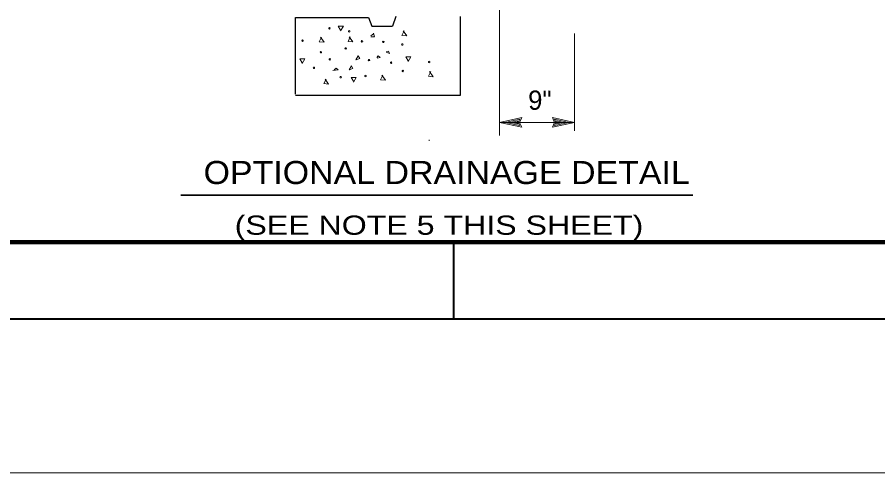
# Model space of a CAD drawing. Extents: x -22.3 to 19.7, y -11.8 to 18.2.
# Drawn here: x -0.15 to 5.45, y -11.84 to -8.88 of the extents above; entities that cross this region are included whole.
import ezdxf
from ezdxf.enums import TextEntityAlignment as Align

# ---------------------------------------------------------------- set-up
doc = ezdxf.new("R2010")
doc.units = 0
doc.header["$LTSCALE"] = 0.05
doc.layers.add('1', color=7, linetype='Continuous', lineweight=13)
doc.layers.add('2', color=7, linetype='Continuous', lineweight=13)

msp = doc.modelspace()

# ---------------------------------------------------------------- linework, layer by layer
at = {"layer": '1'}
for p, q in [((2.99058, -8.52869), (2.99058, -9.64669)), ((3.47858, -8.98169), (3.47858, -9.61469)), ((2.99058, -9.56069), (3.13458, -9.52969)), ((2.99058, -9.56069), (3.47858, -9.56069)), ((2.99058, -9.56069), (3.13458, -9.59169)), ((3.02758, -9.56069), (3.12158, -9.54069)), ((3.02758, -9.56069), (3.12158, -9.58069)), ((3.06358, -9.56069), (3.10858, -9.55069)), ((3.06358, -9.56069), (3.10858, -9.56969)), ((3.10858, -9.55069), (3.10458, -9.56069)), ((3.10458, -9.56069), (3.10858, -9.56969)), ((3.12158, -9.54069), (3.11258, -9.56069)), ((3.11258, -9.56069), (3.12158, -9.58069)), ((3.47858, -9.56069), (3.33458, -9.52969)), ((3.47858, -9.56069), (3.33458, -9.59169)), ((3.44158, -9.56069), (3.34758, -9.54069)), ((3.35658, -9.56069), (3.34758, -9.54069)), ((3.44158, -9.56069), (3.34758, -9.58069)), ((3.34758, -9.58069), (3.35658, -9.56069)), ((3.40558, -9.56069), (3.36058, -9.55169)), ((3.36458, -9.56069), (3.36058, -9.55169)), ((3.40558, -9.56069), (3.36058, -9.57069)), ((3.36058, -9.57069), (3.36458, -9.56069)), ((2.53258, -9.67469), (2.53258, -9.68069)), ((19.69058, -11.83969), (-22.30942, -11.83969))]:
    msp.add_line(p, q, dxfattribs=at)
at = {"layer": '1', "lineweight": 25}
for p, q in [((1.66258, -9.37669), (1.66258, -8.87869)), ((1.66258, -8.87869), (2.13858, -8.87869)), ((2.13858, -8.87869), (2.15858, -8.93469)), ((2.31658, -8.87269), (2.29458, -8.93469)), ((2.73658, -9.38269), (2.73658, -8.87269)), ((2.15858, -8.93469), (2.29458, -8.93469)), ((1.66258, -9.38269), (2.73658, -9.38269))]:
    msp.add_line(p, q, dxfattribs=at)
at = {"layer": '1', "lineweight": 35}
msp.add_line((0.91658, -10.03369), (4.24758, -10.03369), dxfattribs=at)
at = {"layer": '1', "lineweight": 40}
msp.add_line((2.69058, -10.33969), (2.69058, -10.83969), dxfattribs=at)
msp.add_lwpolyline([(-21.30942, -10.83969), (-21.30942, 17.16031), (18.69058, 17.16031), (18.69058, -10.83969)], close=True, dxfattribs=at)
at = {"layer": '1', "lineweight": 90}
msp.add_lwpolyline([(-19.80942, 16.66031), (18.19058, 16.66031), (18.19058, -10.33969), (-19.80942, -10.33969)], close=True, dxfattribs=at)
at = {"layer": '1'}
for points in [[(3.13458, -9.52969), (3.12058, -9.56069), (3.13458, -9.59169)], [(3.33458, -9.59169), (3.34858, -9.56069), (3.33458, -9.52969)]]:
    msp.add_lwpolyline(points, dxfattribs=at)
at = {"layer": '2'}
msp.add_line((2.15358, -8.99869), (2.17058, -8.98369), dxfattribs=at)
for points in [[(1.95658, -8.96069), (1.94158, -8.93569), (1.97458, -8.93569), (1.95658, -8.96569)], [(1.83258, -9.00669), (1.81758, -9.03669), (1.84858, -9.03969), (1.82558, -9.00669)], [(2.01958, -9.00369), (2.00458, -9.03369), (2.03558, -9.03669), (2.01158, -9.00369)], [(2.17058, -8.98069), (2.17658, -9.00369), (2.15358, -9.00369)], [(2.37058, -8.96569), (2.35558, -8.99569), (2.38658, -8.99869), (2.36358, -8.96569)], [(2.25258, -9.10169), (2.26758, -9.09669), (2.27458, -9.11269), (2.25258, -9.10469)], [(1.70658, -9.17369), (1.69158, -9.14769), (1.72458, -9.14769), (1.70658, -9.17869)], [(2.19158, -9.13969), (2.20158, -9.12769), (2.21458, -9.13969), (2.19458, -9.14269)], [(2.39558, -9.16069), (2.38058, -9.13469), (2.41358, -9.13469), (2.39558, -9.16569)], [(1.91358, -9.21869), (1.92858, -9.20869), (1.94158, -9.21869), (1.90658, -9.22369)], [(2.54258, -9.23069), (2.52758, -9.26069), (2.55858, -9.26369), (2.53458, -9.23069)], [(1.86258, -9.27869), (1.84758, -9.30869), (1.87858, -9.31169), (1.85558, -9.27869)], [(2.03958, -9.29369), (2.02458, -9.26869), (2.05758, -9.26869), (2.03958, -9.29969)], [(2.23158, -9.25369), (2.21658, -9.28369), (2.24758, -9.28669), (2.22458, -9.25369)]]:
    msp.add_lwpolyline(points, dxfattribs=at)
for points in [[(2.05658, -9.15369), (2.07158, -9.12769), (2.08058, -9.14569)], [(2.01158, -9.21869), (2.02658, -9.19269), (2.03558, -9.21069)]]:
    msp.add_lwpolyline(points, close=True, dxfattribs=at)
for centre in [(1.88383, -8.94856), (2.01208, -8.96881), (1.70908, -9.02881), (2.09533, -9.03406), (2.23408, -9.03706), (2.35783, -9.05431), (1.82833, -9.10456), (1.98958, -9.07981), (1.88608, -9.15031), (2.14108, -9.15556), (2.28508, -9.17281), (2.53258, -9.16756), (1.78258, -9.20581), (2.36083, -9.22606), (1.95658, -9.26656), (2.11858, -9.25906)]:
    msp.add_circle(centre, 0.00487, dxfattribs=at)

# ---------------------------------------------------------------- texts
at = {"layer": '1'}
msp.add_text('9"', height=0.125, dxfattribs=at).set_placement((3.25258, -9.47869), align=Align.CENTER)
for s, height, width, p in [('OPTIONAL DRAINAGE DETAIL', 0.15, 1.1, (2.64658, -9.96169)), ('(SEE NOTE 5 THIS SHEET)', 0.125, 1.25, (2.59658, -10.29169))]:
    msp.add_text(s, height=height, dxfattribs=dict(at, width=width)).set_placement(p, align=Align.CENTER)

doc.saveas('drawing.dxf')
